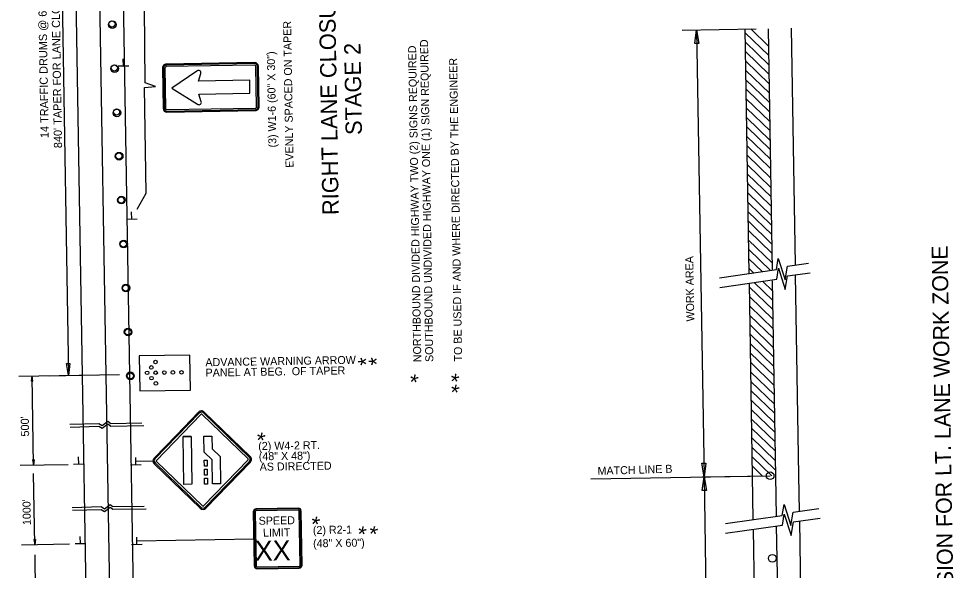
# Model space of a CAD drawing. Extents: x 1676639 to 1677883, y 226447 to 231777.
# Drawn here: x 1677066 to 1677767, y 228980 to 229394 of the extents above; entities that cross this region are included whole.
import ezdxf

# ---------------------------------------------------------------- set-up
doc = ezdxf.new("R2010")
doc.units = 0
for name, color, linetype in [('Default', 7, 'Continuous'), ('P_TC_Signs_Permanent', 7, 'Continuous'), ('R_Annotation', 7, 'Continuous')]:
    doc.layers.add(name, color=color, linetype=linetype)

msp = doc.modelspace()

# ---------------------------------------------------------------- linework, layer by layer
at = {"layer": 'Default'}
for p, q in [((1677131.14, 229126.72), (1677119.09, 229853.64)), ((1677148.87, 229127.01), (1677136.82, 229853.94)), ((1677113.41, 229126.42), (1677101.36, 229853.35)), ((1677095.16, 229587.22), (1677102.8, 229126.25)), ((1677563.04, 229385.3), (1677618.38, 229386.22)), ((1677572.45, 229375.16), (1677573.82, 229385.48)), ((1677573.82, 229385.48), (1677575.54, 229375.21)), ((1677573.82, 229385.48), (1677579.38, 229050.18)), ((1677613.23, 229202.72), (1677610.19, 229386.09)), ((1677627.79, 229373.31), (1677614.5, 229386.16)), ((1677630.58, 229205.18), (1677627.57, 229386.37)), ((1677647.89, 229209.38), (1677644.96, 229386.66)), ((1677627.91, 229366.24), (1677610.24, 229383.33)), ((1677575.54, 229375.21), (1677572.45, 229375.16)), ((1677628.02, 229359.17), (1677610.36, 229376.26)), ((1677144.08, 229358.34), (1677143.99, 229363.79)), ((1677628.14, 229352.1), (1677610.47, 229369.19)), ((1677148.05, 229358.29), (1677140.07, 229358.16)), ((1677628.26, 229345.03), (1677610.59, 229362.12)), ((1677628.38, 229337.96), (1677610.71, 229355.05)), ((1677628.49, 229330.89), (1677610.82, 229347.98)), ((1677628.61, 229323.82), (1677610.94, 229340.91)), ((1677628.73, 229316.75), (1677611.06, 229333.84)), ((1677628.84, 229309.68), (1677611.18, 229326.77)), ((1677628.96, 229302.61), (1677611.29, 229319.7)), ((1677629.08, 229295.53), (1677611.41, 229312.63)), ((1677629.2, 229288.46), (1677611.53, 229305.56)), ((1677629.31, 229281.39), (1677611.64, 229298.49)), ((1677629.43, 229274.32), (1677611.76, 229291.42)), ((1677629.55, 229267.25), (1677611.88, 229284.35)), ((1677629.66, 229260.18), (1677612, 229277.28)), ((1677629.78, 229253.11), (1677612.11, 229270.21)), ((1677629.9, 229246.04), (1677612.23, 229263.14)), ((1677630.02, 229238.97), (1677612.35, 229256.07)), ((1677154.3, 229243.42), (1677146.33, 229243.29)), ((1677150.33, 229243.47), (1677150.24, 229248.92)), ((1677630.13, 229231.9), (1677612.47, 229249)), ((1677630.25, 229224.83), (1677612.58, 229241.93)), ((1677630.37, 229217.76), (1677612.7, 229234.86)), ((1677630.49, 229210.69), (1677612.82, 229227.79)), ((1677629.13, 229205.05), (1677612.93, 229220.72)), ((1677622.83, 229204.19), (1677613.05, 229213.65)), ((1677616.53, 229203.32), (1677613.17, 229206.58)), ((1677650.52, 229051.14), (1677648.02, 229201.73)), ((1677615.75, 229050.78), (1677613.35, 229195.54)), ((1677630.95, 229182.41), (1677616.84, 229196.07)), ((1677630.84, 229189.48), (1677623.14, 229196.93)), ((1677633.14, 229050.37), (1677630.71, 229197.28)), ((1677631.07, 229175.34), (1677613.4, 229192.44)), ((1677631.19, 229168.27), (1677613.52, 229185.37)), ((1677631.31, 229161.2), (1677613.64, 229178.3)), ((1677631.42, 229154.13), (1677613.75, 229171.23)), ((1677631.54, 229147.06), (1677613.87, 229164.16)), ((1677631.66, 229139.99), (1677613.99, 229157.09)), ((1677631.77, 229132.92), (1677614.11, 229150.02)), ((1677631.89, 229125.85), (1677614.22, 229142.94)), ((1677101.32, 229135.09), (1677103.98, 229135.13)), ((1677102.8, 229126.25), (1677101.32, 229135.09)), ((1677103.98, 229135.13), (1677102.8, 229126.25)), ((1677632.01, 229118.78), (1677614.34, 229135.87)), ((1677065.57, 229125.63), (1677141.18, 229126.88)), ((1677075.04, 229121.96), (1677075.55, 229125.79)), ((1677075.14, 229121.96), (1677075.56, 229125.16)), ((1677075.24, 229121.96), (1677075.57, 229124.5)), ((1677076.66, 229059.02), (1677075.55, 229125.79)), ((1677076.19, 229121.98), (1677075.55, 229125.79)), ((1677076.09, 229121.98), (1677075.56, 229125.16)), ((1677076, 229121.98), (1677075.57, 229124.5)), ((1677088.85, 229126.01), (1677124.75, 229126.61)), ((1677116.11, 228963.33), (1677113.41, 229126.42)), ((1677133.84, 228963.62), (1677131.14, 229126.72)), ((1677151.57, 228963.92), (1677148.87, 229127.01)), ((1677632.13, 229111.71), (1677614.46, 229128.8)), ((1677075.04, 229121.96), (1677076.19, 229121.98)), ((1677075.33, 229121.97), (1677075.58, 229123.86)), ((1677075.43, 229121.97), (1677075.6, 229123.21)), ((1677075.53, 229121.97), (1677075.61, 229122.57)), ((1677075.9, 229121.97), (1677075.58, 229123.86)), ((1677075.8, 229121.97), (1677075.6, 229123.21)), ((1677075.71, 229121.97), (1677075.61, 229122.57)), ((1677632.24, 229104.64), (1677614.57, 229121.73)), ((1677632.36, 229097.57), (1677614.69, 229114.66)), ((1677632.48, 229090.5), (1677614.81, 229107.59)), ((1677632.59, 229083.43), (1677614.93, 229100.52)), ((1677632.71, 229076.36), (1677615.04, 229093.45)), ((1677632.83, 229069.29), (1677615.16, 229086.38)), ((1677632.95, 229062.22), (1677614.71, 229079.86)), ((1677633.06, 229055.15), (1677615.4, 229072.24)), ((1677077.17, 229062.86), (1677076.02, 229062.84)), ((1677076.02, 229062.84), (1677076.66, 229059.02)), ((1677076.12, 229062.84), (1677076.65, 229059.66)), ((1677076.22, 229062.84), (1677076.64, 229060.32)), ((1677076.31, 229062.84), (1677076.63, 229060.96)), ((1677076.41, 229062.84), (1677076.62, 229061.6)), ((1677076.51, 229062.85), (1677076.61, 229062.24)), ((1677076.69, 229062.85), (1677076.61, 229062.24)), ((1677076.78, 229062.85), (1677076.62, 229061.6)), ((1677076.88, 229062.85), (1677076.63, 229060.96)), ((1677076.98, 229062.85), (1677076.64, 229060.32)), ((1677077.07, 229062.86), (1677076.65, 229059.66)), ((1677077.17, 229062.86), (1677076.66, 229059.02)), ((1677110.58, 229059.7), (1677110.49, 229065.15)), ((1677153.35, 229059.12), (1677153.26, 229064.57)), ((1677630.14, 229051.02), (1677615.51, 229065.17)), ((1677066.67, 229058.86), (1677102.58, 229059.45)), ((1677114.55, 229059.65), (1677106.58, 229059.52)), ((1677157.32, 229059.07), (1677149.34, 229058.94)), ((1677577.66, 229060.46), (1677580.76, 229060.51)), ((1677579.38, 229050.18), (1677577.66, 229060.46)), ((1677580.76, 229060.51), (1677579.38, 229050.18)), ((1677623.07, 229050.91), (1677615.63, 229058.1)), ((1677077.65, 228999.35), (1677076.77, 229052.57)), ((1677494.51, 229048.77), (1677628.94, 229051)), ((1677577.91, 229050.16), (1677628.94, 229051)), ((1677577.91, 229050.16), (1677628.94, 229051)), ((1677577.91, 229050.16), (1677628.94, 229051)), ((1677578.01, 229039.85), (1677579.38, 229050.18)), ((1677579.38, 229050.18), (1677584.5, 228741.12)), ((1677579.38, 229050.18), (1677581.1, 229039.9)), ((1677616.29, 229018.1), (1677615.75, 229050.78)), ((1677633.64, 229020.56), (1677633.14, 229050.37)), ((1677650.96, 229024.39), (1677650.52, 229051.14)), ((1677581.1, 229039.9), (1677578.01, 229039.85)), ((1677638.27, 228741.31), (1677633.76, 229013.27)), ((1677655.64, 228742.08), (1677651.08, 229017.11)), ((1677111.79, 229000.03), (1677111.7, 229005.48)), ((1677154.12, 228999.45), (1677154.03, 229004.89)), ((1677620.87, 228741.91), (1677616.41, 229010.81)), ((1677067.66, 228999.18), (1677103.57, 228999.78)), ((1677078.16, 229003.18), (1677077.01, 229003.16)), ((1677077.01, 229003.16), (1677077.65, 228999.35)), ((1677077.11, 229003.17), (1677077.64, 228999.99)), ((1677077.2, 229003.17), (1677077.63, 229000.65)), ((1677077.3, 229003.17), (1677077.62, 229001.28)), ((1677077.4, 229003.17), (1677077.61, 229001.93)), ((1677077.5, 229003.17), (1677077.6, 229002.57)), ((1677077.68, 229003.18), (1677077.6, 229002.57)), ((1677077.77, 229003.18), (1677077.61, 229001.93)), ((1677077.87, 229003.18), (1677077.62, 229001.28)), ((1677077.97, 229003.18), (1677077.63, 229000.65)), ((1677078.06, 229003.18), (1677077.64, 228999.99)), ((1677078.16, 229003.18), (1677077.65, 228999.35)), ((1677115.76, 228999.98), (1677107.78, 228999.85)), ((1677158.09, 228999.4), (1677150.11, 228999.26)), ((1677078.66, 228938.47), (1677077.78, 228991.7))]:
    msp.add_line(p, q, dxfattribs=at)
for points in [[(1677154.39, 229251.1), (1677161.14, 229263.02), (1677159.83, 229342.22), (1677168.16, 229343.05), (1677160.47, 229345.7), (1677159.29, 229458.95), (1677147.25, 229471.95)], [(1677591.06, 229199.58), (1677633.73, 229205.63), (1677635.05, 229213.91), (1677640.17, 229197.97), (1677641.94, 229208.2), (1677657.72, 229210.36)], [(1677591.18, 229192.3), (1677633.85, 229198.35), (1677635.17, 229206.63), (1677640.29, 229190.68), (1677642.06, 229200.91), (1677658.88, 229203.22)], [(1677103.92, 229089.57), (1677125.65, 229090.26), (1677128.14, 229088.64), (1677132.5, 229091.94), (1677134.57, 229090.28), (1677157.99, 229090.66)], [(1677104.15, 229087.54), (1677125.6, 229088.22), (1677128.09, 229086.6), (1677132.45, 229089.9), (1677134.51, 229088.24), (1677159.46, 229088.65)], [(1677105.6, 229027.11), (1677127.33, 229027.8), (1677129.82, 229026.19), (1677134.18, 229029.49), (1677136.24, 229027.82), (1677159.67, 229028.21)], [(1677105.83, 229025.08), (1677127.27, 229025.76), (1677129.77, 229024.15), (1677134.13, 229027.45), (1677136.19, 229025.78), (1677161.14, 229026.19)], [(1677595.4, 229015.13), (1677638.06, 229021.18), (1677639.38, 229029.46), (1677644.5, 229013.52), (1677646.28, 229023.75), (1677665.44, 229026.38)], [(1677595.52, 229007.85), (1677638.18, 229013.9), (1677639.5, 229022.18), (1677644.62, 229006.24), (1677646.4, 229016.46), (1677666.43, 229019.21)]]:
    msp.add_lwpolyline(points, dxfattribs=at)
msp.add_lwpolyline([(1677156.36, 229114.63), (1677194.33, 229115.26), (1677193.9, 229141.54), (1677155.92, 229140.91)], close=True, dxfattribs=at)
for centre, radius in [((1677135.74, 229389.48), 2.87), ((1677135.48, 229389.85), 2.33), ((1677137.47, 229356.36), 2.87), ((1677137.2, 229356.86), 2.33), ((1677139.21, 229323.23), 2.87), ((1677138.92, 229323.87), 2.33), ((1677140.87, 229290.73), 2.87), ((1677140.63, 229290.87), 2.33), ((1677142.55, 229257.77), 2.87), ((1677142.35, 229257.88), 2.33), ((1677144.23, 229224.81), 2.87), ((1677144.07, 229224.89), 2.33), ((1677145.9, 229191.85), 2.87), ((1677145.78, 229191.9), 2.33), ((1677147.58, 229158.9), 2.87), ((1677147.5, 229158.91), 2.33), ((1677164.98, 229132.24), 1.34), ((1677168.14, 229136.32), 1.34), ((1677149.26, 229125.94), 2.87), ((1677149.22, 229125.92), 2.33), ((1677149.21, 229125.8), 2.33), ((1677161.82, 229128.16), 1.34), ((1677165.12, 229124.19), 1.34), ((1677168.27, 229128.27), 1.34), ((1677174.72, 229128.38), 1.34), ((1677181.17, 229128.48), 1.34), ((1677187.62, 229128.59), 1.34), ((1677168.41, 229120.22), 1.34), ((1677628.94, 229051), 2.87), ((1677630.55, 228989.03), 2.87)]:
    msp.add_circle(centre, radius, dxfattribs=at)
at = {"layer": 'P_TC_Signs_Permanent'}
for p, q in [((1677173.32, 229356.95), (1677173.82, 229326.57)), ((1677174.07, 229356.96), (1677174.57, 229326.59)), ((1677175.19, 229356.98), (1677175.69, 229326.61)), ((1677242.45, 229360.9), (1677176.08, 229359.8)), ((1677242.46, 229360.15), (1677176.09, 229359.05)), ((1677242.48, 229359.03), (1677176.11, 229357.93)), ((1677243.94, 229327.74), (1677243.43, 229358.11)), ((1677245.06, 229327.76), (1677244.56, 229358.13)), ((1677245.81, 229327.77), (1677245.31, 229358.14)), ((1677176.65, 229325.68), (1677243.01, 229326.78)), ((1677176.67, 229324.56), (1677243.03, 229325.66)), ((1677176.68, 229323.81), (1677243.04, 229324.91)), ((1677204.69, 229098.76), (1677239.19, 229065.39)), ((1677194.83, 229080.54), (1677188.83, 229080.44)), ((1677239.26, 229061.15), (1677205.88, 229026.65)), ((1677201.64, 229026.58), (1677167.14, 229059.95)), ((1677275.11, 229026.68), (1677243.61, 229026.16)), ((1677275.12, 229026.12), (1677243.62, 229025.59)), ((1677241.4, 229023.87), (1677242.07, 228983.38)), ((1677241.96, 229023.88), (1677242.63, 228983.38)), ((1677242.9, 229023.89), (1677243.57, 228983.4)), ((1677275.13, 229025.18), (1677243.63, 229024.66)), ((1677276.56, 228983.95), (1677275.89, 229024.44)), ((1677277.5, 228983.96), (1677276.83, 229024.46)), ((1677278.06, 228983.97), (1677277.39, 229024.47)), ((1677244.33, 228982.66), (1677275.83, 228983.19)), ((1677244.35, 228981.73), (1677275.84, 228982.25)), ((1677244.36, 228981.16), (1677275.85, 228981.69))]:
    msp.add_line(p, q, dxfattribs=at)
for points in [[(1677199.1, 229354.63), (1677180.32, 229341.87), (1677199.52, 229329.78)], [(1677202.44, 229331.6), (1677200.63, 229337.33), (1677238.89, 229337.97), (1677238.73, 229347.72), (1677200.47, 229347.08), (1677202.12, 229352.86)], [(1677167.07, 229064.2), (1677183.76, 229081.44), (1677200.45, 229098.69)], [(1677201.09, 229098.07), (1677167.72, 229063.57)], [(1677168.8, 229062.53), (1677202.17, 229097.03)], [(1677203.02, 229097.04), (1677237.52, 229063.67)], [(1677238.56, 229064.74), (1677204.06, 229098.12)], [(1677203.31, 229028.3), (1677168.81, 229061.68)], [(1677237.53, 229062.82), (1677204.16, 229028.32)], [(1677205.24, 229027.28), (1677238.61, 229061.77)], [(1677167.77, 229060.6), (1677202.27, 229027.23)]]:
    msp.add_lwpolyline(points, dxfattribs=at)
for points in [[(1677195.43, 229044.54), (1677189.43, 229044.44), (1677188.83, 229080.44), (1677194.83, 229080.54)], [(1677216.96, 229044.9), (1677210.96, 229044.8), (1677210.66, 229062.8), (1677204.57, 229068.7), (1677204.37, 229080.69), (1677210.37, 229080.79), (1677210.52, 229071.28), (1677216.62, 229065.38)], [(1677206.84, 229058.23), (1677204.74, 229058.2), (1677204.67, 229062.7), (1677206.77, 229062.73)], [(1677206.95, 229051.48), (1677204.85, 229051.45), (1677204.78, 229055.95), (1677206.88, 229055.98)], [(1677207.06, 229044.73), (1677204.96, 229044.7), (1677204.89, 229049.2), (1677206.99, 229049.23)]]:
    msp.add_lwpolyline(points, close=True, dxfattribs=at)
for centre, radius, start, end in [((1677176.13, 229356.99), 2.81, 90.94971, 180.94971), ((1677176.13, 229356.99), 2.06, 90.94971, 180.94971), ((1677176.13, 229356.99), 0.938, 90.94971, 180.94971), ((1677242.49, 229358.09), 2.81, 0.94971, 90.94971), ((1677242.49, 229358.09), 2.06, 0.94971, 90.94971), ((1677242.49, 229358.09), 0.938, 0.94971, 90.94971), ((1677156.97, 229416.67), 75, 304.17831, 304.42519), ((1677200.39, 229353.33), 1.8, 344.98064, 124.42519), ((1677159.56, 229266.31), 75, 57.54915, 57.80668), ((1677200.75, 229331.09), 1.76, 237.54915, 16.91879), ((1677243, 229327.72), 0.937, 270.94971, 0.94971), ((1677243, 229327.72), 2.06, 270.94971, 0.94971), ((1677243, 229327.72), 2.81, 270.94971, 0.94971), ((1677176.63, 229326.62), 2.81, 180.94971, 270.94971), ((1677176.63, 229326.62), 2.06, 180.94971, 270.94971), ((1677176.63, 229326.62), 0.938, 180.94971, 270.94971), ((1677202.6, 229096.61), 3, 45.94971, 135.94971), ((1677202.6, 229096.61), 2.1, 45.94971, 135.94971), ((1677202.6, 229096.61), 0.6, 45.94971, 135.94971), ((1677169.23, 229062.11), 3, 135.94971, 225.94971), ((1677169.23, 229062.11), 2.1, 135.94971, 225.94971), ((1677169.23, 229062.11), 0.6, 135.94971, 225.94971), ((1677237.1, 229063.23), 0.6, 315.94971, 45.94971), ((1677237.1, 229063.23), 2.1, 315.94971, 45.94971), ((1677237.1, 229063.23), 3, 315.94971, 45.94971), ((1677203.73, 229028.74), 3, 225.94971, 315.94971), ((1677203.73, 229028.74), 2.1, 225.94971, 315.94971), ((1677203.73, 229028.74), 0.6, 225.94971, 315.94971), ((1677243.65, 229023.91), 2.25, 90.94971, 180.94971), ((1677275.14, 229024.43), 2.25, 0.94971, 90.94971), ((1677275.14, 229024.43), 1.69, 0.94971, 90.94971), ((1677243.65, 229023.91), 1.69, 90.94971, 180.94971), ((1677243.65, 229023.91), 0.75, 90.94971, 180.94971), ((1677275.14, 229024.43), 0.75, 0.94971, 90.94971), ((1677275.81, 228983.93), 0.75, 270.94971, 0.94971), ((1677275.81, 228983.93), 1.69, 270.94971, 0.94971), ((1677275.81, 228983.93), 2.25, 270.94971, 0.94971), ((1677244.32, 228983.41), 2.25, 180.94971, 270.94971), ((1677244.32, 228983.41), 1.69, 180.94971, 270.94971), ((1677244.32, 228983.41), 0.75, 180.94971, 270.94971)]:
    msp.add_arc(centre, radius, start, end, dxfattribs=at)
at = {"layer": 'R_Annotation'}
for p, q in [((1677153.3, 229061.85), (1677166.23, 229062.06)), ((1677154.08, 229002.17), (1677241.73, 229003.62))]:
    msp.add_line(p, q, dxfattribs=at)

# ---------------------------------------------------------------- texts
at = {"layer": 'Default'}
for s, height, p in [('DIVERSION FOR LT. LANE WORK ZONE', 12, (1677767, 228919.9)), ("500'", 6.12, (1677073.39, 229080.4)), ("1000'", 6, (1677074.69, 229013.99))]:
    msp.add_text(s, height=height, rotation=90.94971, dxfattribs=at).set_placement(p)
at = {"layer": 'P_TC_Signs_Permanent'}
for s, height, p in [('SPEED', 6, (1677245.49, 229014.19)), ('LIMIT', 6, (1677248.73, 229005.24)), ('XX', 15, (1677242.71, 228987.14))]:
    msp.add_text(s, height=height, rotation=0.94971, dxfattribs=at).set_placement(p)
at = {"layer": 'R_Annotation'}
for s, height, rotation, p in [("840' TAPER FOR LANE CLOSURE", 6.1199, 90.94971, (1677098.11, 229296.81)), ('RIGHT LANE CLOSURE', 12.2398, 90.94971, (1677305.55, 229246.67)), ("14 TRAFFIC DRUMS @ 60' O.C.", 6.1199, 90.94971, (1677088.06, 229304.35)), ('EVENLY SPACED ON TAPER', 6, 90.95726, (1677271.63, 229282.13)), ('SOUTHBOUND UNDIVIDED HIGHWAY ONE (1) SIGN REQUIRED', 6, 90.94971, (1677376.42, 229136.37)), ('STAGE 2', 12.24, 90.94971, (1677322.91, 229306.72)), ('NORTHBOUND DIVIDED HIGHWAY TWO (2) SIGNS REQUIRED ', 6, 90.94971, (1677367.42, 229136.22)), ('(3) W1-6 (60" X 30")', 6, 90.95726, (1677258.77, 229297.29)), ('TO BE USED IF AND WHERE DIRECTED BY THE ENGINEER', 6, 90.94971, (1677398.01, 229136.73)), ('WORK AREA', 6, 90.94971, (1677572.07, 229166.74)), ('ADVANCE WARNING ARROW', 6, 0.94971, (1677205.57, 229133.09)), ('*', 12, 90.94971, (1677332.06, 229133.69)), ('*', 12, 90.94971, (1677339.99, 229133.82)), ('PANEL AT BEG.  OF TAPER', 6, 0.94971, (1677205.7, 229125.3)), ('*', 12, 135.94971, (1677370.49, 229128.09)), ('*', 12, 135.94971, (1677401.08, 229128.59)), ('*', 12, 135.94971, (1677401.21, 229120.41)), ('*', 12, 135.94971, (1677255.73, 229084.48)), ('(2) W4-2 RT.', 6, 0.94971, (1677245.2, 229070.26)), ('(48" X 48")', 6, 0.94971, (1677245.59, 229062.54)), ('AS DIRECTED ', 6, 0.94971, (1677246.29, 229054.68)), ('MATCH LINE B', 6, 1.75564, (1677499.62, 229051.56)), ('*', 12, 135.94971, (1677296.67, 229021.41)), ('(2) R2-1', 6, 0.94971, (1677286.15, 229007.19)), ('*', 12, 135.94971, (1677331.56, 229014.03)), ('*', 12, 135.94971, (1677340.09, 229014.17)), ('(48" X 60")', 6, 0.94971, (1677286.31, 228997.22))]:
    msp.add_text(s, height=height, rotation=rotation, dxfattribs=at).set_placement(p)

doc.saveas('drawing.dxf')
